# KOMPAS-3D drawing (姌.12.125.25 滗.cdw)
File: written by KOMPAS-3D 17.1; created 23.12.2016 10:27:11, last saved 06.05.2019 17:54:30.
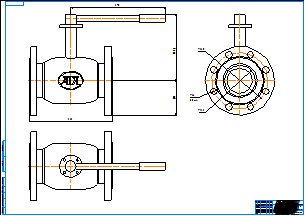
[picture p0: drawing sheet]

Sheet 1: A0, landscape

Title block, sheet 1: name: КШ.12.125.25 фф; material: Внимание! Данный продукт является объектом авторского права ООО «Торговый Дом АДЛ». / Запрещается изменение, копирование, распространение / (в том числе путем копирования на другие сайты и ресурсы в Интернете) / или любое иное использование информации и объектов без предварительного / согласия правообладателя (ООО «Торговый Дом АДЛ»).; sheets: 1; organisation: ООО "Торговый дом АДЛ"; sheet format: A0; stored path: C:\Users\tra\Desktop\2д чертежи\Шаровые краны БИВАЛ\КШ_Бивал_серия_11_12\KOMPAS_2D\КШ.12.125.25 фф.cdw

Views: Вид 1, Проекционный вид 2, Проекционный вид 3
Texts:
  Klimkovich
  ADL
Dimensions and other numbers on the sheet: 325; 370; 258,4; 135; 220; 123; 26; 8 Отв.; 1:1; 1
